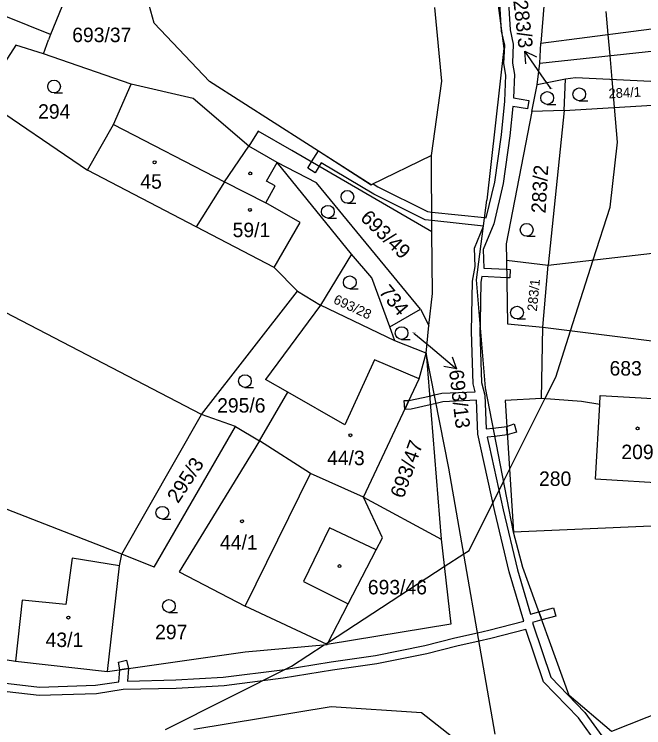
# Model space of a CAD drawing. Extents: x -747333 to -745433, y -1133152 to -1130600.
# Drawn here: x -746298.7 to -746224.7, y -1132218.2 to -1132134.3 of the extents above; entities that cross this region are included whole.
import ezdxf

# ---------------------------------------------------------------- set-up
doc = ezdxf.new("R2010")
doc.units = 0
for name, color, linetype in [('Vrstva 1', 7, 'Continuous'), ('Vrstva 16', 7, 'Continuous'), ('Vrstva 18', 7, 'Continuous'), ('Vrstva 19', 7, 'Continuous'), ('Vrstva 25', 7, 'Continuous'), ('Vrstva 3', 7, 'Continuous'), ('Vrstva 30', 7, 'Continuous'), ('Vrstva 37', 7, 'Continuous'), ('Vrstva 4', 7, 'Continuous'), ('Vrstva 52', 7, 'Continuous'), ('Vrstva 6', 7, 'Continuous')]:
    doc.layers.add(name, color=color, linetype=linetype)

msp = doc.modelspace()

# ---------------------------------------------------------------- linework, layer by layer
at = {"layer": 'Vrstva 1'}
for points in [[(-746284.28, -1132111.82), (-746294.42, -1132136.7)], [(-746235.45, -1132121.74), (-746236.75, -1132137.7)], [(-746282.24, -1132135.36), (-746284.17, -1132128.28)], [(-746241.88, -1132132.35), (-746241.11, -1132138.34)], [(-746248.4, -1132142.18), (-746249.24, -1132133.5)], [(-746236.75, -1132137.7), (-746214.96, -1132134.88)], [(-746275.7, -1132142.21), (-746282.24, -1132135.36)], [(-746294.42, -1132136.7), (-746294.66, -1132137.31)], [(-746295.24, -1132138.98), (-746294.66, -1132137.31)], [(-746236.89, -1132140.06), (-746236.75, -1132137.7)], [(-746298.49, -1132137.94), (-746300.91, -1132141.67)], [(-746295.24, -1132138.98), (-746298.49, -1132137.94)], [(-746241.11, -1132138.34), (-746243.12, -1132156.17)], [(-746284.93, -1132142.52), (-746295.24, -1132138.98)], [(-746237.17, -1132142.63), (-746236.89, -1132140.06)], [(-746233.85, -1132141.94), (-746237.17, -1132142.63)], [(-746234.03, -1132145.62), (-746233.85, -1132141.94)], [(-746232.7, -1132141.79), (-746233.85, -1132141.94)], [(-746207.7, -1132143.01), (-746232.7, -1132141.79)], [(-746286.99, -1132147.28), (-746284.93, -1132142.52)], [(-746277.62, -1132144.21), (-746284.93, -1132142.52)], [(-746256.69, -1132154.37), (-746275.7, -1132142.21)], [(-746249.63, -1132150.94), (-746248.4, -1132142.18)], [(-746237.82, -1132145.77), (-746237.17, -1132142.63)], [(-746302.53, -1132144.17), (-746290.06, -1132152.64)], [(-746271.08, -1132149.84), (-746277.62, -1132144.21)], [(-746234.03, -1132145.62), (-746222.33, -1132144.91)], [(-746237.82, -1132145.77), (-746240.84, -1132161.3)], [(-746234.03, -1132145.62), (-746237.82, -1132145.77)], [(-746234.03, -1132145.62), (-746235.89, -1132163.82)], [(-746290.06, -1132152.64), (-746286.99, -1132147.28)], [(-746269.98, -1132148.07), (-746271.08, -1132149.84)], [(-746266.05, -1132150.32), (-746269.98, -1132148.07)], [(-746273.97, -1132154.01), (-746271.08, -1132149.84)], [(-746267.76, -1132151.76), (-746271.08, -1132149.84)], [(-746249.58, -1132159.89), (-746266.05, -1132150.32)], [(-746249.63, -1132150.94), (-746256.69, -1132154.37)], [(-746249.58, -1132159.89), (-746249.63, -1132150.94)], [(-746263.14, -1132154.13), (-746267.76, -1132151.76)], [(-746259.02, -1132162.52), (-746267.76, -1132151.76)], [(-746277.28, -1132159.31), (-746290.06, -1132152.64)], [(-746273.97, -1132154.01), (-746277.28, -1132159.31)], [(-746250.91, -1132168.99), (-746263.14, -1132154.13)], [(-746244.31, -1132165.56), (-746243.12, -1132156.17)], [(-746235.89, -1132163.82), (-746181.68, -1132157.61)], [(-746268.1, -1132164.11), (-746277.28, -1132159.31)], [(-746249.5, -1132167.15), (-746249.58, -1132159.89)], [(-746276.66, -1132181.4), (-746316.09, -1132160.88)], [(-746240.84, -1132161.3), (-746240.81, -1132163.25)], [(-746259.02, -1132162.52), (-746262.67, -1132168.54)], [(-746256.61, -1132165.3), (-746259.02, -1132162.52)], [(-746240.81, -1132163.25), (-746235.89, -1132163.82)], [(-746240.81, -1132163.25), (-746240.67, -1132170.74)], [(-746265.37, -1132166.88), (-746268.1, -1132164.11)], [(-746236.54, -1132171.13), (-746235.89, -1132163.82)], [(-746254.52, -1132171.09), (-746256.61, -1132165.3)], [(-746243.27, -1132178.27), (-746244.31, -1132165.56)], [(-746276.66, -1132181.4), (-746265.37, -1132166.88)], [(-746265.37, -1132166.88), (-746262.67, -1132168.54)], [(-746249.91, -1132170.92), (-746249.5, -1132167.15)], [(-746262.67, -1132168.54), (-746269.15, -1132177.26)], [(-746253.91, -1132172.73), (-746262.67, -1132168.54)], [(-746254.52, -1132171.09), (-746250.91, -1132168.99)], [(-746250.91, -1132168.99), (-746249.91, -1132170.92)], [(-746253.91, -1132172.73), (-746254.52, -1132171.09)], [(-746250.26, -1132174.19), (-746249.91, -1132170.92)], [(-746240.67, -1132170.74), (-746236.54, -1132171.13)], [(-746236.67, -1132179.5), (-746236.54, -1132171.13)], [(-746236.54, -1132171.13), (-746214.63, -1132173.86)], [(-746250.26, -1132174.19), (-746253.91, -1132172.73)], [(-746251.07, -1132177.2), (-746250.26, -1132174.19)], [(-746250.26, -1132174.19), (-746248.47, -1132196.06)], [(-746247.56, -1132187.7), (-746250.26, -1132174.19)], [(-746266.52, -1132178.78), (-746269.15, -1132177.26)], [(-746257.62, -1132191.11), (-746251.07, -1132177.2)], [(-746269.83, -1132184.49), (-746266.52, -1132178.78)], [(-746239.96, -1132195.24), (-746243.27, -1132178.27)], [(-746236.67, -1132179.5), (-746240.97, -1132179.73)], [(-746231.98, -1132179.88), (-746236.67, -1132179.5)], [(-746229.84, -1132180.22), (-746229.78, -1132179.17)], [(-746229.78, -1132179.17), (-746223.6, -1132179.52)], [(-746240.97, -1132179.73), (-746239.96, -1132195.24)], [(-746229.84, -1132180.22), (-746231.98, -1132179.88)], [(-746230.33, -1132189), (-746229.84, -1132180.22)], [(-746286.03, -1132197.8), (-746276.66, -1132181.4)], [(-746272.66, -1132182.81), (-746276.66, -1132181.4)], [(-746282.24, -1132199.36), (-746272.66, -1132182.81)], [(-746272.66, -1132182.81), (-746269.83, -1132184.49)], [(-746269.83, -1132184.49), (-746279.28, -1132199.88)], [(-746263.83, -1132188.34), (-746269.83, -1132184.49)], [(-746242.13, -1132218.98), (-746247.56, -1132187.7)], [(-746257.62, -1132191.11), (-746263.83, -1132188.34)], [(-746286.03, -1132197.8), (-746307.91, -1132189.33)], [(-746221.34, -1132189.53), (-746230.33, -1132189)], [(-746255.38, -1132195.9), (-746257.62, -1132191.11)], [(-746257.62, -1132191.11), (-746248.47, -1132196.06)], [(-746190.47, -1132193.09), (-746239.96, -1132195.24)], [(-746238.89, -1132199.39), (-746239.96, -1132195.24)], [(-746256.11, -1132197.3), (-746255.38, -1132195.9)], [(-746248.47, -1132196.06), (-746247.35, -1132206.07)], [(-746259.4, -1132203.66), (-746256.11, -1132197.3)], [(-746286.31, -1132199.21), (-746286.03, -1132197.8)], [(-746282.24, -1132199.36), (-746286.03, -1132197.8)], [(-746287.72, -1132211.62), (-746286.31, -1132199.21)], [(-746233.44, -1132214.44), (-746238.89, -1132199.39)], [(-746279.28, -1132199.88), (-746271.52, -1132203.95)], [(-746261.88, -1132208.46), (-746271.52, -1132203.95)], [(-746261.88, -1132208.46), (-746259.4, -1132203.66)], [(-746247.35, -1132206.07), (-746261.88, -1132208.46)], [(-746311.91, -1132208.23), (-746298.54, -1132210.41)], [(-746271.53, -1132209.32), (-746261.88, -1132208.46)], [(-746287.72, -1132211.62), (-746271.53, -1132209.32)], [(-746298.54, -1132210.41), (-746287.72, -1132211.62)], [(-746228.44, -1132218.67), (-746233.44, -1132214.44)], [(-746218.08, -1132214.58), (-746228.44, -1132218.67)], [(-746277.54, -1132218.41), (-746261.41, -1132215.72)], [(-746261.41, -1132215.72), (-746250.79, -1132216.43)], [(-746250.79, -1132216.43), (-746239.72, -1132225.13)]]:
    msp.add_lwpolyline(points, dxfattribs=at)
at = {"layer": 'Vrstva 16'}
for p, q in [((-746238.506092, -1132140.160093), (-746238.631576, -1132138.664515)), ((-746247.188601, -1132174.59882), (-746246.673633, -1132176.008539))]:
    msp.add_line(p, q, dxfattribs=at)
for points in [[(-746236.35, -1132141.95), (-746238.631576, -1132138.664515), (-746237.274036, -1132139.304502)], [(-746235.56, -1132143.09), (-746236.35, -1132141.95)], [(-746251.69, -1132171.81), (-746249.74, -1132173.44)], [(-746249.74, -1132173.44), (-746246.673633, -1132176.008539), (-746248.151803, -1132175.748707)]]:
    msp.add_lwpolyline(points, dxfattribs=at)
at = {"layer": 'Vrstva 25'}
for p, q in [((-746293.99, -1132143.56), (-746292.99, -1132143.56)), ((-746236.01, -1132144.91), (-746235.01, -1132144.91)), ((-746232.24, -1132144.48), (-746231.24, -1132144.48)), ((-746259.5, -1132156.54), (-746258.5, -1132156.54)), ((-746261.8, -1132158.29), (-746260.8, -1132158.29)), ((-746238.42, -1132160.42), (-746237.42, -1132160.42)), ((-746259.22, -1132166.6), (-746258.22, -1132166.6)), ((-746239.56, -1132170.15), (-746238.56, -1132170.15)), ((-746253.13, -1132172.56), (-746252.13, -1132172.56)), ((-746271.55, -1132178.21), (-746270.55, -1132178.21)), ((-746281.26, -1132193.7), (-746280.26, -1132193.7)), ((-746280.49, -1132204.67), (-746279.49, -1132204.67))]:
    msp.add_line(p, q, dxfattribs=at)
for centre, radius in [((-746293.99, -1132142.81), 0.75), ((-746236.01, -1132144.16), 0.75), ((-746232.24, -1132143.73), 0.75), ((-746282.18, -1132151.73), 0.174503), ((-746270.93, -1132153.04), 0.174503), ((-746259.5, -1132155.79), 0.75), ((-746261.8, -1132157.54), 0.75), ((-746270.97, -1132157.33), 0.174503), ((-746238.42, -1132159.67), 0.75), ((-746259.22, -1132165.85), 0.75), ((-746239.56, -1132169.4), 0.75), ((-746253.13, -1132171.81), 0.75), ((-746271.55, -1132177.46), 0.75), ((-746225.38, -1132183.03), 0.174503), ((-746259.15, -1132183.83), 0.174503), ((-746281.26, -1132192.95), 0.75), ((-746271.89, -1132193.95), 0.174503), ((-746260.43, -1132199.22), 0.174503), ((-746280.49, -1132203.92), 0.75), ((-746292.31, -1132205.28), 0.174503)]:
    msp.add_circle(centre, radius, dxfattribs=at)
at = {"layer": 'Vrstva 3'}
for points in [[(-746290.06, -1132152.64), (-746286.99, -1132147.28)], [(-746286.99, -1132147.28), (-746273.97, -1132154.01)], [(-746277.28, -1132159.31), (-746290.06, -1132152.64)], [(-746273.97, -1132154.01), (-746277.28, -1132159.31)], [(-746273.97, -1132154.01), (-746277.28, -1132159.31)], [(-746273.97, -1132154.01), (-746269.1, -1132156.5)], [(-746265.06, -1132158.79), (-746269.1, -1132156.5)], [(-746268.1, -1132164.11), (-746277.28, -1132159.31)], [(-746268.1, -1132164.11), (-746265.06, -1132158.79)], [(-746256.3, -1132174.95), (-746259.81, -1132182.62)], [(-746251.07, -1132177.2), (-746256.3, -1132174.95)], [(-746257.62, -1132191.11), (-746251.07, -1132177.2)], [(-746269.83, -1132184.49), (-746266.52, -1132178.78)], [(-746259.81, -1132182.62), (-746266.52, -1132178.78)], [(-746229.84, -1132180.22), (-746229.78, -1132179.17)], [(-746229.78, -1132179.17), (-746223.6, -1132179.52)], [(-746230.33, -1132189), (-746229.84, -1132180.22)], [(-746269.83, -1132184.49), (-746279.28, -1132199.88)], [(-746263.83, -1132188.34), (-746269.83, -1132184.49)], [(-746263.83, -1132188.34), (-746269.83, -1132184.49)], [(-746271.52, -1132203.95), (-746263.83, -1132188.34)], [(-746257.62, -1132191.11), (-746263.83, -1132188.34)], [(-746221.34, -1132189.53), (-746230.33, -1132189)], [(-746291.88, -1132198.29), (-746292.59, -1132203.73)], [(-746286.31, -1132199.21), (-746291.88, -1132198.29)], [(-746287.72, -1132211.62), (-746286.31, -1132199.21)], [(-746279.28, -1132199.88), (-746271.52, -1132203.95)], [(-746297.74, -1132203.24), (-746298.54, -1132210.41)], [(-746292.59, -1132203.73), (-746297.74, -1132203.24)], [(-746298.54, -1132210.41), (-746287.72, -1132211.62)]]:
    msp.add_lwpolyline(points, dxfattribs=at)
at = {"layer": 'Vrstva 30'}
for points in [[(-746241.37, -1132136.3), (-746242, -1132125.85)], [(-746241, -1132125.85), (-746240.38, -1132136.16)], [(-746241.01, -1132137.93), (-746241.37, -1132136.3)], [(-746240.38, -1132136.16), (-746240.01, -1132137.83)], [(-746241.1, -1132140.11), (-746241.01, -1132137.93)], [(-746240.01, -1132137.83), (-746240.1, -1132140.05)], [(-746240.87, -1132141.46), (-746241.1, -1132140.11)], [(-746240.1, -1132140.05), (-746239.87, -1132141.4)], [(-746241.01, -1132144.53), (-746240.87, -1132141.46)], [(-746239.87, -1132141.4), (-746239.99, -1132144.15)], [(-746239.99, -1132144.15), (-746238.18, -1132144.45)], [(-746238.18, -1132144.45), (-746238.34, -1132145.43)], [(-746241.39, -1132148.49), (-746241.01, -1132144.53)], [(-746240.07, -1132145.15), (-746240.39, -1132148.61)], [(-746238.34, -1132145.43), (-746240.07, -1132145.15)], [(-746242.16, -1132154.05), (-746241.39, -1132148.49)], [(-746240.39, -1132148.61), (-746241.18, -1132154.23)], [(-746263.71, -1132151.68), (-746262.91, -1132150.39)], [(-746262.91, -1132150.39), (-746256.69, -1132154.37)], [(-746264.17, -1132152.43), (-746263.71, -1132151.68)], [(-746262.84, -1132152.18), (-746263.71, -1132151.68)], [(-746263.71, -1132151.68), (-746262.84, -1132152.18)], [(-746262.59, -1132151.77), (-746262.84, -1132152.18)], [(-746256.4, -1132155.49), (-746262.59, -1132151.77)], [(-746263.31, -1132152.96), (-746264.17, -1132152.43)], [(-746262.84, -1132152.18), (-746263.31, -1132152.96)], [(-746256.69, -1132154.37), (-746256.49, -1132154.27)], [(-746256.49, -1132154.27), (-746255.92, -1132154.61)], [(-746243.17, -1132158.26), (-746242.16, -1132154.05)], [(-746241.18, -1132154.23), (-746242.3, -1132158.95)], [(-746255.92, -1132154.61), (-746250.09, -1132157.53)], [(-746250.37, -1132158.51), (-746256.4, -1132155.49)], [(-746250.09, -1132157.53), (-746249.59, -1132157.58)], [(-746249.59, -1132157.58), (-746243.38, -1132158.23)], [(-746249.59, -1132158.59), (-746250.37, -1132158.51)], [(-746243.51, -1132159.23), (-746249.59, -1132158.59)], [(-746243.38, -1132158.23), (-746243.17, -1132158.26)], [(-746244.55, -1132161.81), (-746243.51, -1132159.23)], [(-746242.3, -1132158.95), (-746243.55, -1132161.99)], [(-746244.47, -1132163.99), (-746244.55, -1132161.81)], [(-746243.55, -1132161.99), (-746243.46, -1132164.16)], [(-746244.81, -1132165.72), (-746244.47, -1132163.99)], [(-746243.46, -1132164.16), (-746240.79, -1132164.3)], [(-746240.79, -1132164.3), (-746240.37, -1132164.32)], [(-746240.37, -1132164.32), (-746240.42, -1132165.32)], [(-746243.69, -1132165.14), (-746243.81, -1132165.82)], [(-746240.77, -1132165.3), (-746243.69, -1132165.14)], [(-746240.42, -1132165.32), (-746240.77, -1132165.3)], [(-746244.93, -1132171.63), (-746244.81, -1132165.72)], [(-746243.81, -1132165.82), (-746243.91, -1132170.49)], [(-746243.91, -1132170.49), (-746243.93, -1132171.63)], [(-746244.73, -1132177.78), (-746244.93, -1132171.63)], [(-746243.93, -1132171.63), (-746243.73, -1132177.62)], [(-746244.49, -1132178.72), (-746244.73, -1132177.78)], [(-746243.73, -1132177.62), (-746243.35, -1132179.12)], [(-746248.41, -1132178.9), (-746244.49, -1132178.72)], [(-746252.28, -1132179.76), (-746249.85, -1132179.22)], [(-746249.85, -1132179.22), (-746249.28, -1132179.09)], [(-746249.28, -1132179.09), (-746248.41, -1132178.9)], [(-746243.35, -1132179.12), (-746243.19, -1132183.08)], [(-746252.76, -1132180.79), (-746252.83, -1132179.76)], [(-746252.83, -1132179.76), (-746252.28, -1132179.76)], [(-746252.76, -1132180.79), (-746252.28, -1132179.76)], [(-746252.28, -1132179.76), (-746252.76, -1132180.79)], [(-746249.76, -1132180.24), (-746252.02, -1132180.76)], [(-746249.08, -1132180.08), (-746249.76, -1132180.24)], [(-746248.29, -1132179.9), (-746249.08, -1132180.08)], [(-746244.32, -1132179.72), (-746248.29, -1132179.9)], [(-746244.16, -1132183.7), (-746244.32, -1132179.72)], [(-746252.02, -1132180.76), (-746252.76, -1132180.79)], [(-746243.19, -1132183.08), (-746242.35, -1132182.98)], [(-746242.35, -1132182.98), (-746240.77, -1132182.79)], [(-746240.77, -1132182.79), (-746239.9, -1132182.49)], [(-746240.77, -1132182.79), (-746240.71, -1132183.78)], [(-746240.71, -1132183.78), (-746240.77, -1132182.79)], [(-746239.9, -1132182.49), (-746239.62, -1132183.45)], [(-746243.83, -1132185.3), (-746244.16, -1132183.7)], [(-746240.71, -1132183.78), (-746242.16, -1132183.96)], [(-746239.62, -1132183.45), (-746240.71, -1132183.78)], [(-746242.16, -1132183.96), (-746243.06, -1132184.07)], [(-746243.06, -1132184.07), (-746242.85, -1132185.08)], [(-746242.18, -1132192.81), (-746243.83, -1132185.3)], [(-746242.85, -1132185.08), (-746241.2, -1132192.59)], [(-746240.48, -1132199.91), (-746242.18, -1132192.81)], [(-746241.2, -1132192.59), (-746239.52, -1132199.65)], [(-746239.52, -1132199.65), (-746237.96, -1132204.88)], [(-746238.75, -1132205.72), (-746240.48, -1132199.91)], [(-746237.96, -1132204.88), (-746237, -1132204.61)], [(-746237, -1132204.61), (-746235.27, -1132204.14)], [(-746237, -1132204.61), (-746236.66, -1132205.56)], [(-746236.66, -1132205.56), (-746237, -1132204.61)], [(-746235.27, -1132204.14), (-746235.01, -1132205.1)], [(-746242.86, -1132206.77), (-746238.75, -1132205.72)], [(-746236.66, -1132205.56), (-746237.72, -1132205.85)], [(-746235.01, -1132205.1), (-746236.66, -1132205.56)], [(-746237.72, -1132205.85), (-746237.67, -1132206.13)], [(-746237.67, -1132206.13), (-746235.57, -1132212.3)], [(-746246.86, -1132207.68), (-746244.2, -1132207.08)], [(-746244.2, -1132207.08), (-746242.86, -1132206.77)], [(-746238.53, -1132206.7), (-746242.62, -1132207.75)], [(-746236.45, -1132212.84), (-746238.53, -1132206.7)], [(-746250.4, -1132208.57), (-746246.86, -1132207.68)], [(-746244.02, -1132208.07), (-746246.63, -1132208.66)], [(-746242.62, -1132207.75), (-746244.02, -1132208.07)], [(-746256.2, -1132209.73), (-746250.4, -1132208.57)], [(-746246.63, -1132208.66), (-746250.18, -1132209.55)], [(-746261.41, -1132210.49), (-746256.2, -1132209.73)], [(-746250.18, -1132209.55), (-746256.04, -1132210.71)], [(-746286.43, -1132210.51), (-746285.46, -1132210.3)], [(-746286.24, -1132211.41), (-746286.43, -1132210.51)], [(-746285.46, -1132210.3), (-746285.24, -1132211.27)], [(-746267.19, -1132211.43), (-746261.41, -1132210.49)], [(-746256.04, -1132210.71), (-746261.25, -1132211.47)], [(-746286.37, -1132212.82), (-746286.24, -1132211.41)], [(-746286.24, -1132211.41), (-746285.24, -1132211.27)], [(-746285.24, -1132211.27), (-746286.24, -1132211.41)], [(-746285.24, -1132211.27), (-746285.35, -1132212.74)], [(-746274.1, -1132212.3), (-746267.19, -1132211.43)], [(-746261.25, -1132211.47), (-746267.04, -1132212.41)], [(-746279.67, -1132212.61), (-746274.1, -1132212.3)], [(-746267.04, -1132212.41), (-746274, -1132213.3)], [(-746235.57, -1132212.3), (-746231.57, -1132216.43)], [(-746300.71, -1132212.89), (-746295.7, -1132213.45)], [(-746295.7, -1132213.45), (-746289.11, -1132213.24)], [(-746289.11, -1132213.24), (-746286.37, -1132212.82)], [(-746285.35, -1132212.74), (-746279.67, -1132212.61)], [(-746232.33, -1132217.07), (-746236.45, -1132212.84)], [(-746295.74, -1132214.45), (-746300.93, -1132213.87)], [(-746285.86, -1132213.75), (-746289.01, -1132214.24)], [(-746279.63, -1132213.61), (-746285.86, -1132213.75)], [(-746274, -1132213.3), (-746279.63, -1132213.61)], [(-746289.01, -1132214.24), (-746295.74, -1132214.45)], [(-746231.57, -1132216.43), (-746229.17, -1132219.78)], [(-746230.03, -1132220.28), (-746232.33, -1132217.07)]]:
    msp.add_lwpolyline(points, dxfattribs=at)
at = {"layer": 'Vrstva 37'}
for centre in [(-746282.18, -1132151.73), (-746270.97, -1132157.33), (-746225.38, -1132183.03), (-746259.15, -1132183.83), (-746271.89, -1132193.95), (-746292.31, -1132205.28)]:
    msp.add_circle(centre, 0.174503, dxfattribs=at)
at = {"layer": 'Vrstva 4'}
for points in [[(-746294.42, -1132136.7), (-746302.51, -1132133.44)], [(-746286.99, -1132147.28), (-746273.97, -1132154.01)], [(-746269.01, -1132153.93), (-746267.76, -1132151.76)], [(-746273.97, -1132154.01), (-746269.1, -1132156.5)], [(-746269.1, -1132156.5), (-746267.99, -1132154.49)], [(-746267.99, -1132154.49), (-746269.01, -1132153.93)], [(-746265.06, -1132158.79), (-746269.1, -1132156.5)], [(-746268.1, -1132164.11), (-746265.06, -1132158.79)], [(-746256.3, -1132174.95), (-746259.81, -1132182.62)], [(-746251.07, -1132177.2), (-746256.3, -1132174.95)], [(-746259.81, -1132182.62), (-746266.52, -1132178.78)], [(-746271.52, -1132203.95), (-746263.83, -1132188.34)], [(-746261.59, -1132194.74), (-746264.68, -1132201.02)], [(-746256.11, -1132197.3), (-746261.59, -1132194.74)], [(-746291.88, -1132198.29), (-746292.59, -1132203.73)], [(-746286.31, -1132199.21), (-746291.88, -1132198.29)], [(-746264.68, -1132201.02), (-746259.4, -1132203.66)], [(-746297.74, -1132203.24), (-746298.54, -1132210.41)], [(-746292.59, -1132203.73), (-746297.74, -1132203.24)]]:
    msp.add_lwpolyline(points, dxfattribs=at)
at = {"layer": 'Vrstva 52'}
msp.add_lwpolyline([(-746280.9, -1132218.43), (-746266.06, -1132211), (-746262.22, -1132208.49), (-746261.88, -1132208.46), (-746262.05, -1132208.38), (-746261.73, -1132208.17), (-746248.11, -1132199.28), (-746245.81, -1132197.78), (-746245.19, -1132197.37), (-746241.13, -1132189.26), (-746240.44, -1132187.88), (-746236.27, -1132179.53), (-746235, -1132177), (-746233.26, -1132171.54), (-746230.61, -1132163.21), (-746228.62, -1132157), (-746227.75, -1132149.37), (-746228.1, -1132145.26), (-746228.38, -1132142), (-746228.62, -1132139.17), (-746228.83, -1132136.68), (-746229.06, -1132134)], dxfattribs=at)
at = {"layer": 'Vrstva 6'}
msp.add_lwpolyline([(-746236.89, -1132140.06), (-746208.09, -1132136.95)], dxfattribs=at)

# ---------------------------------------------------------------- texts
at = {"layer": 'Vrstva 16'}
for s, rotation, p in [('283/3', 276.42222, (-746240.002027, -1132132.714285)), ('693/13', 276.76962, (-746247.558148, -1132176.210392))]:
    msp.add_text(s, height=1.7, rotation=rotation, dxfattribs=at).set_placement(p)
at = {"layer": 'Vrstva 18'}
for s, height, p in [('693/37', 1.7, (-746291.86, -1132137.59)), ('283/3', 0.1, (-746235.747225, -1132143.09)), ('294', 1.7, (-746295.87, -1132146.6)), ('693/13', 0.1, (-746251.903555, -1132171.81)), ('683', 1.7, (-746228.68, -1132176.81)), ('295/6', 1.7, (-746274.820072, -1132181.17)), ('280', 1.7, (-746236.97, -1132189.79)), ('693/46', 1.7, (-746257.1, -1132202.55)), ('297', 1.7, (-746282.11, -1132207.82))]:
    msp.add_text(s, height=height, dxfattribs=at).set_placement(p)
for s, height, rotation, p in [('284/1', 1.14, 3.19455, (-746228.77, -1132144.21)), ('283/2', 1.7, 86.71077, (-746236.2, -1132157.76)), ('693/49', 1.7, 315.93159, (-746258.09, -1132158.39)), ('734', 1.7, 309.87513, (-746255.885767, -1132167.020439)), ('283/1', 1.14, 84.35943, (-746237.23, -1132169.29)), ('693/28', 1.14, 334.93797, (-746261.24, -1132168.26)), ('693/47', 1.7, 70.24815, (-746252.92, -1132191.36)), ('295/3', 1.7, 56.6919, (-746279.41, -1132191.93))]:
    msp.add_text(s, height=height, rotation=rotation, dxfattribs=at).set_placement(p)
at = {"layer": 'Vrstva 19'}
for s, p in [('45', (-746283.85, -1132154.83)), ('59/1', (-746273, -1132160.53)), ('44/3', (-746261.89, -1132187.35)), ('209', (-746227.29, -1132186.64)), ('44/1', (-746274.48, -1132197.28)), ('43/1', (-746294.99, -1132208.74))]:
    msp.add_text(s, height=1.7, dxfattribs=at).set_placement(p)

doc.saveas('drawing.dxf')
